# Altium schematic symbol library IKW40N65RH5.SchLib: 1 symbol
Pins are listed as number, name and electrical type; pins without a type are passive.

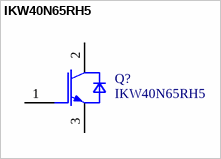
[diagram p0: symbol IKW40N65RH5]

## IKW40N65RH5
designator Q?
Isolated-Gate Bipolar Transistor (IGBT), N-Channel, Depletion, Body Diode, Pin 1 Gate, 2 Collector, 3 Emitter, 3 Pins; Manufacturer: Infineon Technologies
pins: 1 GATE, 2 COLLECTOR, 3 EMITTER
